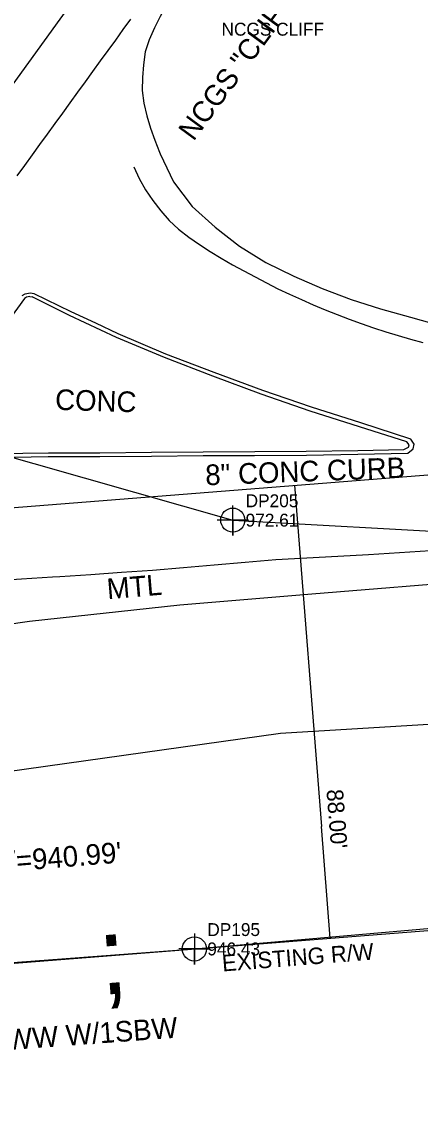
# Model space of a CAD drawing. Extents: x 1182322 to 1186765, y 572295 to 575411.
# Drawn here: x 1184379.6 to 1184456.8, y 573641.9 to 573854 of the extents above; entities that cross this region are included whole.
import ezdxf

# ---------------------------------------------------------------- set-up
doc = ezdxf.new("R2010")
doc.units = 0
for name, color, linetype in [('COGO Default Chain', 7, 'Continuous'), ('Exist Guardrail', 7, 'Continuous'), ('Exist Guardrail Text', 7, 'Continuous'), ('Exist Horizontal Alignment', 7, 'Continuous'), ('Exist Other Culture Fence Line', 7, 'Continuous'), ('Exist Other Culture Fence Line Cogo Elevation', 7, 'Continuous'), ('Exist Other Culture Fence Line Cogo Number', 7, 'Continuous'), ('Exist Other Culture Fence Line Cogo Point CELL', 7, 'Continuous'), ('Exist Other Culture Fence Line Text', 7, 'Continuous'), ('Exist Property Iron Pin Cogo Comment', 7, 'Continuous'), ('Exist Property Iron Pin Text', 7, 'Continuous'), ('Exist Right of Way Control of Access CA Symbol CELL', 7, 'Continuous'), ('Exist Right of Way Line', 7, 'Continuous'), ('Exist Right of Way Line Text', 7, 'Continuous'), ('Exist Right of Way Width CELL', 7, 'Continuous'), ('Exist Roads Curbs', 7, 'Continuous'), ('Exist Roads Curbs Text', 7, 'Continuous'), ('Exist Roads EOP', 7, 'Continuous'), ('Exist Roads EOP Text', 7, 'Continuous'), ('Exist Roads EOT', 7, 'Continuous'), ('Exist Structure Minor Pipes RCP 24 Inch Invert', 7, 'Continuous'), ('Exist Utilities Telephone UG Conduit SUE LOS B', 7, 'Continuous'), ('Exist Utilities Telephone UG Conduit SUE LOS B Cogo Elevation', 7, 'Continuous'), ('Exist Utilities Telephone UG Conduit SUE LOS B Cogo Number', 7, 'Continuous'), ('Exist Utilities Telephone UG Conduit SUE LOS B Cogo Point CELL', 7, 'Continuous'), ('Exist Vegetation Woods Line', 7, 'Continuous')]:
    doc.layers.add(name, color=color, linetype=linetype)

msp = doc.modelspace()

# ---------------------------------------------------------------- linework, layer by layer
at = {"layer": 'COGO Default Chain'}
for p, q in [((1184334.34, 573781.86), (1184678.73, 574257.66)), ((1184314.88, 573754.98), (1184895.31, 573800.93))]:
    msp.add_line(p, q, dxfattribs=at)
at = {"layer": 'Exist Guardrail'}
msp.add_lwpolyline([(1184594.84, 573755.66), (1184581.2, 573754.58), (1184547.52, 573751.95), (1184509.98, 573749.08), (1184469.15, 573745.92), (1184435.77, 573743.21), (1184410.17, 573741.05), (1184381.08, 573737.92), (1184359.98, 573734.84), (1184343.19, 573731.95), (1184332.72, 573729), (1184325.59, 573725.67), (1184320.11, 573721.72), (1184312.32, 573714.54), (1184307.06, 573708.76), (1184300.35, 573700.18), (1184274.63, 573665.56), (1184242.6, 573621.44), (1184211.01, 573578.54), (1184178.56, 573533.74), (1184149.85, 573494.36), (1184125.97, 573461.42), (1184110.36, 573439.47)], dxfattribs=at)
at = {"layer": 'Exist Horizontal Alignment'}
for p, q in [((1184334.34, 573781.86), (1184678.73, 574257.66)), ((1184314.88, 573754.98), (1184895.31, 573800.93))]:
    msp.add_line(p, q, dxfattribs=at)
at = {"layer": 'Exist Other Culture Fence Line'}
msp.add_lwpolyline([(1184315.15, 573667.2), (1184359.8, 573670.48), (1184413.02, 573674.46), (1184464.84, 573679.03), (1184511.18, 573683.63), (1184622.99, 573691.06), (1184699.34, 573697.51), (1184773.78, 573703.02)], dxfattribs=at)
at = {"layer": 'Exist Other Culture Fence Line Cogo Point CELL'}
msp.add_lwpolyline([(1184413.02, 573677.46), (1184413.02, 573671.46), (1184413.02, 573674.46), (1184416.02, 573674.46), (1184410.02, 573674.46)], dxfattribs=at)
msp.add_circle((1184413.02, 573674.46), 2.34, dxfattribs=at)
at = {"layer": 'Exist Right of Way Control of Access CA Symbol CELL'}
msp.add_line((1184401.79, 573673.59), (1184401.79, 573673.59), dxfattribs=at)
at = {"layer": 'Exist Right of Way Line'}
msp.add_line((1184312.49, 573666.52), (1184902.25, 573713.2), dxfattribs=at)
at = {"layer": 'Exist Right of Way Width CELL'}
for p in [(1184432.41, 573764.28), (1184439.35, 573676.56)]:
    msp.add_line(p, (1184437.64, 573698.15), dxfattribs=at)
at = {"layer": 'Exist Roads Curbs'}
for p, q in [((1184381.1, 573800.87), (1184380.48, 573800.73)), ((1184381.1, 573800.87), (1184381.56, 573800.76)), ((1184380.47, 573800.73), (1184380.07, 573800.45)), ((1184453.58, 573771.2), (1184454.49, 573771.65)), ((1184454.62, 573772.14), (1184454.17, 573772.69)), ((1184454.49, 573771.66), (1184454.62, 573772.13))]:
    msp.add_line(p, q, dxfattribs=at)
for points in [[(1184380.07, 573800.45), (1184374.09, 573792.24), (1184368.24, 573784.13), (1184362.18, 573776.18), (1184359.08, 573771.9)], [(1184454.16, 573772.69), (1184444.99, 573775.58), (1184435.48, 573778.67), (1184425.99, 573781.96), (1184416.61, 573785.44), (1184407.22, 573789.04), (1184397.95, 573792.93), (1184388.81, 573797.19), (1184381.56, 573800.76)], [(1184359.87, 573770.33), (1184374.71, 573770.41), (1184384.71, 573770.55), (1184394.71, 573770.57), (1184404.71, 573770.7), (1184414.71, 573770.79), (1184424.71, 573770.84), (1184434.71, 573770.91), (1184444.71, 573771.04), (1184453.58, 573771.2)]]:
    msp.add_lwpolyline(points, dxfattribs=at)
at = {"layer": 'Exist Roads EOP'}
for p, q in [((1184380.16, 573801.29), (1184379.59, 573800.97)), ((1184381.24, 573801.5), (1184380.16, 573801.29)), ((1184381.93, 573801.35), (1184381.24, 573801.5)), ((1184454.4, 573770.5), (1184455.39, 573771.33)), ((1184455.6, 573772.26), (1184454.96, 573773.19)), ((1184455.39, 573771.33), (1184455.6, 573772.25))]:
    msp.add_line(p, q, dxfattribs=at)
for points in [[(1184410.38, 573861.44), (1184408.98, 573859.4), (1184407.58, 573857.28), (1184406.38, 573855.12), (1184405.31, 573852.87), (1184404.28, 573850.59), (1184403.47, 573848.23), (1184403.17, 573845.75), (1184402.94, 573843.26), (1184402.89, 573840.77), (1184403.24, 573838.3), (1184403.77, 573835.86), (1184404.5, 573833.48), (1184405.34, 573831.12), (1184406.26, 573828.8), (1184406.38, 573828.51)], [(1184406.39, 573828.48), (1184408.99, 573823.08), (1184412.61, 573818.3), (1184417.05, 573814.27), (1184421.79, 573810.6), (1184426.89, 573807.44), (1184432.28, 573804.81), (1184437.77, 573802.38), (1184443.39, 573800.3), (1184449.1, 573798.47), (1184454.89, 573796.88), (1184460.66, 573795.25), (1184466.43, 573793.58), (1184472.23, 573792.08), (1184478.07, 573790.71), (1184482.52, 573789.78)], [(1184454.95, 573773.19), (1184445.26, 573776.35), (1184435.73, 573779.41), (1184426.25, 573782.67), (1184416.86, 573786.12), (1184407.48, 573789.68), (1184398.26, 573793.65), (1184393.9, 573795.66), (1184389.14, 573797.87), (1184381.94, 573801.35)], [(1184359.83, 573769.62), (1184374.73, 573769.69), (1184384.69, 573769.83), (1184394.72, 573769.85), (1184404.71, 573769.94), (1184414.74, 573770.03), (1184424.69, 573770.07), (1184434.72, 573770.13), (1184444.72, 573770.29), (1184454.39, 573770.5)], [(1184476.7, 573753.02), (1184470.72, 573752.54), (1184464.74, 573752.06), (1184458.76, 573751.58), (1184452.77, 573751.18), (1184446.78, 573750.84), (1184440.79, 573750.5), (1184434.8, 573750.16), (1184428.81, 573749.82), (1184422.83, 573749.32), (1184416.85, 573748.81), (1184410.88, 573748.3), (1184404.9, 573747.79), (1184398.91, 573747.37), (1184392.93, 573746.96), (1184386.94, 573746.56), (1184385.54, 573746.47)], [(1184385.5, 573746.47), (1184379.52, 573746.08), (1184373.53, 573745.69), (1184367.59, 573744.84), (1184361.7, 573743.71), (1184355.77, 573742.75), (1184349.94, 573741.37), (1184349.54, 573741.26)]]:
    msp.add_lwpolyline(points, dxfattribs=at)
at = {"layer": 'Exist Roads EOT'}
for points in [[(1184378.68, 573824.24), (1184380.15, 573826.26), (1184381.62, 573828.28), (1184383.09, 573830.3), (1184384.56, 573832.32), (1184386.03, 573834.35), (1184387.49, 573836.37), (1184388.96, 573838.39), (1184390.43, 573840.41), (1184391.9, 573842.44), (1184393.36, 573844.46), (1184394.83, 573846.48), (1184396.3, 573848.51), (1184397.76, 573850.53), (1184399.23, 573852.55), (1184400.69, 573854.58)], [(1184401.31, 573825.97), (1184402.34, 573823.69), (1184403.55, 573821.51), (1184404.95, 573819.44), (1184406.49, 573817.47), (1184408.15, 573815.6), (1184409.96, 573813.88), (1184411.93, 573812.34), (1184413.99, 573810.93), (1184416.09, 573809.57), (1184418.21, 573808.26), (1184420.38, 573807.01), (1184422.57, 573805.81), (1184424.78, 573804.64), (1184427, 573803.5), (1184429.22, 573802.36), (1184431.48, 573801.29), (1184433.76, 573800.25), (1184436.04, 573799.23), (1184438.35, 573798.27), (1184440.68, 573797.37), (1184443.02, 573796.49), (1184445.36, 573795.63), (1184447.71, 573794.78), (1184450.09, 573794.01), (1184452.48, 573793.27), (1184454.88, 573792.57), (1184457.29, 573791.91)]]:
    msp.add_lwpolyline(points, dxfattribs=at)
at = {"layer": 'Exist Utilities Telephone UG Conduit SUE LOS B'}
msp.add_lwpolyline([(1184322.33, 573794.9), (1184362.8, 573773.9), (1184420.45, 573757.53), (1184467.17, 573754.95), (1184515.32, 573735.91), (1184558.77, 573733.46), (1184577.16, 573728), (1184617.5, 573724.19), (1184669.81, 573719.04), (1184705.2, 573717.51), (1184761.61, 573719.92)], dxfattribs=at)
at = {"layer": 'Exist Utilities Telephone UG Conduit SUE LOS B Cogo Point CELL'}
msp.add_lwpolyline([(1184420.43, 573760.34), (1184420.46, 573754.53), (1184420.45, 573757.53), (1184423.46, 573757.53), (1184417.46, 573757.53)], dxfattribs=at)
msp.add_circle((1184420.46, 573757.53), 2.34, dxfattribs=at)
at = {"layer": 'Exist Vegetation Woods Line'}
msp.add_lwpolyline([(1184428.35, 573532.1), (1184403.72, 573573.78), (1184384.15, 573614.08), (1184368.48, 573629.2), (1184348.41, 573639.47), (1184327.32, 573630.13), (1184286.8, 573598.15), (1184228.4, 573520.48), (1184187.73, 573488.6), (1184178.44, 573486.8), (1184174.62, 573488.17), (1184234.18, 573569.36), (1184276, 573620.06), (1184320.6, 573682.94), (1184353.74, 573705.58), (1184429.72, 573716.26), (1184519.09, 573721.7), (1184575.02, 573729.05)], dxfattribs=at)

# ---------------------------------------------------------------- texts
at = {"layer": 'Exist Guardrail Text'}
msp.add_text('MTL', height=4, rotation=4.8102, dxfattribs=at).set_placement((1184396.21, 573742.19))
at = {"layer": 'Exist Other Culture Fence Line Cogo Elevation'}
msp.add_text('946.43', height=2.5, dxfattribs=at).set_placement((1184415.52, 573673.21))
at = {"layer": 'Exist Other Culture Fence Line Cogo Number'}
msp.add_text('DP195', height=2.5, dxfattribs=at).set_placement((1184415.52, 573676.96))
at = {"layer": 'Exist Other Culture Fence Line Text'}
msp.add_text('48" WW W/1SBW', height=4, rotation=4.198, dxfattribs=at).set_placement((1184367.38, 573654.16))
at = {"layer": 'Exist Property Iron Pin Cogo Comment'}
msp.add_text('NCGS CLIFF', height=2.5, dxfattribs=at).set_placement((1184418.27, 573851.38))
at = {"layer": 'Exist Property Iron Pin Text'}
msp.add_text('NCGS "CLIFF"', height=4, rotation=53.6841, dxfattribs=at).set_placement((1184412.86, 573830.79))
at = {"layer": 'Exist Right of Way Control of Access CA Symbol CELL'}
msp.add_text(';', height=15, rotation=4.5264, dxfattribs=at).set_placement((1184394.91, 573665.52))
at = {"layer": 'Exist Right of Way Line Text'}
msp.add_text('EXISTING R/W', height=3.2, rotation=4.5263, dxfattribs=at).set_placement((1184418.49, 573670.09))
at = {"layer": 'Exist Right of Way Width CELL'}
msp.add_text("88.00'", height=3.2, rotation=274.5263, dxfattribs=at).set_placement((1184438.61, 573705.28))
at = {"layer": 'Exist Roads Curbs Text'}
msp.add_text('8" CONC CURB', height=4, rotation=2.174, dxfattribs=at).set_placement((1184415.2, 573764.27))
at = {"layer": 'Exist Roads EOP Text'}
msp.add_text('CONC', height=4, rotation=358.1784, dxfattribs=at).set_placement((1184385.98, 573778.91))
at = {"layer": 'Exist Structure Minor Pipes RCP 24 Inch Invert'}
msp.add_text("INV=940.99'", height=4, rotation=4.5903, dxfattribs=at).set_placement((1184369.73, 573688.86))
at = {"layer": 'Exist Utilities Telephone UG Conduit SUE LOS B Cogo Elevation'}
msp.add_text('972.61', height=2.5, dxfattribs=at).set_placement((1184422.95, 573756.28))
at = {"layer": 'Exist Utilities Telephone UG Conduit SUE LOS B Cogo Number'}
msp.add_text('DP205', height=2.5, dxfattribs=at).set_placement((1184422.95, 573760.03))

doc.saveas('drawing.dxf')
